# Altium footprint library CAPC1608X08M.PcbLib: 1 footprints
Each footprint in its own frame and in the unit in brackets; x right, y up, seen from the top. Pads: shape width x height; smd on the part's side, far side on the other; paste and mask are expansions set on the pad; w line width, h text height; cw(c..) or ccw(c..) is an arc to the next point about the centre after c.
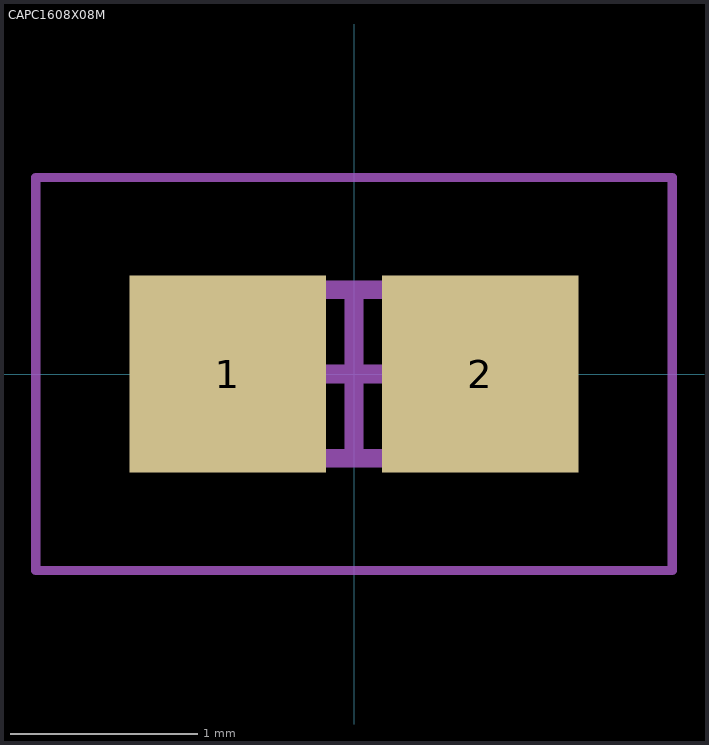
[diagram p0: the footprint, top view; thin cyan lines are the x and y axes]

## CAPC1608X08M [mm] "Chip Capacitor, 2-Leads, Body 1,60x0,80mm, IPC Low Density"
height 0.8
pads (2):
  rect 1.05x1.05 smd: 1(-0.675,0) 2(0.675,0)
Mechanical 13:
  lines w0.1: -0.85,-0.45 0.85,-0.45 0.85,0.45 -0.85,0.45 -0.85,-0.45
Mechanical 15:
  lines w0.05: -1.7,-1.05 1.7,-1.05 1.7,1.05 -1.7,1.05 -1.7,-1.05
  lines w0.1: -0.45,0 0.45,0 ; 0,-0.45 0,0.45
3D body: height 0.8, standoff 0, extent 0.41,-0.45 0.85,0.45
3D body: height 0.8, standoff 0, extent -0.85,-0.45 -0.41,0.45
3D body: height 0.8, standoff 0, extent -0.41,-0.45 0.41,0.45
